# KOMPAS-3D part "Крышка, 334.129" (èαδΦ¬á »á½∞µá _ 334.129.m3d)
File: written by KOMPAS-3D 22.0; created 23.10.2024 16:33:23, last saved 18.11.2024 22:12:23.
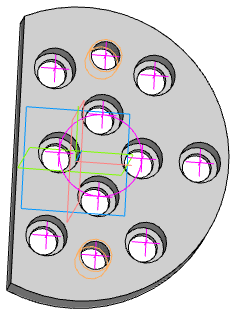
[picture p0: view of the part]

Document properties: Автор: aleksander.larionov.10@gmail.com; Полное имя файла: C:\Мои папки\Работа\Крышки, фланцы\334.129\Крышка пальца _ 334.129.m3d

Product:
- Part/product: Крышка  | designation 334.129
    Материал: Сталь 45 ГОСТ 1050-2013 (density 7810 kg/m3)
    Масса: 1.350551

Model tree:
1. Эскиз:1
2. Элемент выдавливания:1
     Расстояние 1 = 18
3. Эскиз:2  (with: Элемент выдавливания:1)
4. Отверстие:1  (with: Элемент выдавливания:1)
     Глубина выреза = 18; Диаметр отверстия = 14; Угол конуса дна = 118; Расстояние 1 = 16; Расстояние 2 = 41; Диаметр цековки = 20; Глубина цековки = 13
5. Массив по точкам:1
6. Экземпляр ( 3 )  (with: Отверстие:1, Эскиз:2)
7. Экземпляр ( 2 )  (with: Отверстие:1, Эскиз:2)
8. Экземпляр ( 6 )  (with: Отверстие:1, Эскиз:2)
9. Экземпляр ( 8 )  (with: Отверстие:1, Эскиз:2)
10. Экземпляр ( 7 )  (with: Отверстие:1, Эскиз:2)
11. Экземпляр ( 1 )  (with: Отверстие:1, Эскиз:2)
12. Экземпляр ( 4 )  (with: Отверстие:1, Эскиз:2)
13. Экземпляр ( 5 )  (with: Отверстие:1, Эскиз:2)
14. Отверстие:2  (with: Элемент выдавливания:1)  (labels: M16)
     Глубина выреза = 18; Диаметр отверстия = 13.8349; Угол конуса дна = 118; Расстояние 1 = 40; Расстояние 2 = -49
15. M16  (with: Элемент выдавливания:1)  (labels: M16; cil0_24705-2004 coarse)
     Длина резьбы = 18; Шаг резьбы = 2; Номинальный диаметр резьбы = 16
16. Отверстие:3  (with: Элемент выдавливания:1, M16)  (labels: M16; cil0_24705-2004 coarse; Сталь 45 ГОСТ 1050-2013)
     Глубина выреза = 18; Диаметр отверстия = 13.8349; Угол конуса дна = 118; Расстояние 1 = 40; Расстояние 2 = 49; Длина резьбы = 18; Шаг резьбы = 2; Номинальный диаметр резьбы = 16

Referenced files in C:\Program Files\ASCON\KOMPAS-3D v21\Libs\EasySteel\: Rolled metal.kle, StandartSolutions.kle, DSTVProperties.lpt
Referenced files in C:\Program Files\ASCON\KOMPAS-3D v21\Templates\: Констр. чертеж А3 гориз. перв. лист.cdt
Referenced files in C:\Program Files\ASCON\KOMPAS-3D v21\Libs\EasySteel\BeltEndings\: 
Referenced files in C:\Program Files\ASCON\KOMPAS-3D v21\Libs\EasySteel\Punctures\: 
Referenced files in C:\Program Files\ASCON\KOMPAS-3D v21\Libs\EasySteel\Insulations\: 
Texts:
  Уголок равнополочный по ГОСТ 8509-93 (Спец)
  config2DpacketName
  config2DstdSizeID
  Констр. чертеж А3 гориз. перв. лист.cdt
  Болт ГОСТ 22353-77
  Шайба ГОСТ 22355-77
  Гайка ГОСТ 22354-77
  Нормальная пружинная шайба ГОСТ 6402-70 (исп. 1)
  SeaRox SL 436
